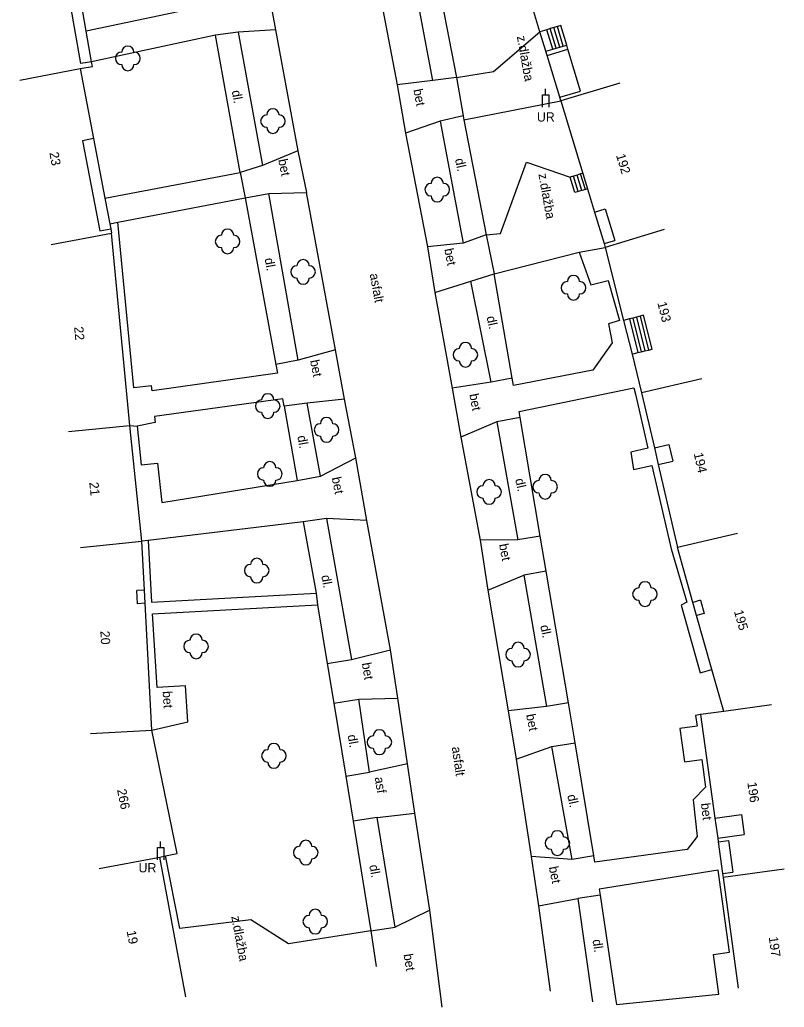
# Model space of a CAD drawing. Extents: x -544674 to -541478, y -1199076 to -1195527.
# Drawn here: x -542529.1 to -542467, y -1198998.4 to -1198918.3 of the extents above; entities that cross this region are included whole.
import ezdxf

# ---------------------------------------------------------------- set-up
doc = ezdxf.new("R2010")
doc.units = 0
for name, color, linetype in [('BUDOVY_MĚŘ', 7, 'Continuous'), ('POMOC_POPIS', 7, 'Continuous'), ('ROZHRANÍ_PLOCH', 7, 'Continuous'), ('ZELEŇ', 7, 'Continuous'), ('ZN_DOPLŇKOVÉ', 7, 'Continuous'), ('Č_POPIS_ORIENT', 7, 'Continuous')]:
    doc.layers.add(name, color=color, linetype=linetype)

msp = doc.modelspace()

# ---------------------------------------------------------------- linework, layer by layer
at = {"layer": 'BUDOVY_MĚŘ'}
for points in [[(-542486.85, -1198919.29), (-542489.77, -1198909.53)], [(-542523.66, -1198919.25), (-542524.33, -1198915.46)], [(-542523.23, -1198921.72), (-542523.66, -1198919.25)], [(-542486.37, -1198920.88), (-542486.85, -1198919.29)], [(-542486.27, -1198921.21), (-542486.37, -1198920.88)], [(-542485.25, -1198924.61), (-542486.27, -1198921.21)], [(-542529.06, -1198923.21), (-542524.15, -1198922.27)], [(-542524.15, -1198922.27), (-542523.16, -1198922.1), (-542523.23, -1198921.72)], [(-542524.15, -1198922.27), (-542523.07, -1198927.96)], [(-542480.38, -1198923.46), (-542485.17, -1198924.89)], [(-542485.17, -1198924.89), (-542485.25, -1198924.61)], [(-542485.17, -1198924.89), (-542483.38, -1198930.78)], [(-542523.07, -1198927.96), (-542522.15, -1198932.8)], [(-542483.38, -1198930.78), (-542483, -1198932.03)], [(-542483, -1198932.03), (-542482.42, -1198933.92)], [(-542522.15, -1198932.8), (-542521.76, -1198934.87)], [(-542482.42, -1198933.92), (-542481.64, -1198936.48)], [(-542521.76, -1198934.87), (-542521.68, -1198935.27)], [(-542521.68, -1198935.27), (-542521.61, -1198935.62)], [(-542526.52, -1198936.55), (-542521.61, -1198935.62)], [(-542520.12, -1198951.23), (-542521.61, -1198935.62)], [(-542476.77, -1198935.32), (-542481.55, -1198936.78)], [(-542481.64, -1198936.48), (-542481.55, -1198936.78)], [(-542481.55, -1198936.78), (-542480.07, -1198942.7)], [(-542480.07, -1198942.7), (-542479.38, -1198945.44)], [(-542479.38, -1198945.44), (-542478.6, -1198948.57)], [(-542473.73, -1198947.44), (-542478.6, -1198948.57)], [(-542478.6, -1198948.57), (-542477.57, -1198953.03)], [(-542525.1, -1198951.71), (-542520.12, -1198951.23)], [(-542519.16, -1198960.62), (-542520.12, -1198951.23)], [(-542477.57, -1198953.03), (-542477.26, -1198954.39)], [(-542477.26, -1198954.39), (-542475.7, -1198961.12)], [(-542470.83, -1198959.99), (-542475.7, -1198961.12)], [(-542524.13, -1198961.13), (-542519.16, -1198960.62)], [(-542518.95, -1198964.57), (-542519.16, -1198960.62)], [(-542474.44, -1198965.58), (-542475.7, -1198961.12)], [(-542518.89, -1198965.65), (-542518.95, -1198964.57)], [(-542518.33, -1198975.93), (-542518.89, -1198965.65)], [(-542474.14, -1198966.64), (-542474.44, -1198965.58)], [(-542472.9, -1198971.01), (-542474.14, -1198966.64)], [(-542471.94, -1198974.42), (-542472.9, -1198971.01)], [(-542471.94, -1198974.42), (-542473.82, -1198974.68)], [(-542468.07, -1198973.88), (-542471.94, -1198974.42)], [(-542473.82, -1198974.68), (-542472.66, -1198983.07)], [(-542523.32, -1198976.2), (-542518.33, -1198975.93)], [(-542517.23, -1198986.14), (-542516.29, -1198985.95), (-542518.33, -1198975.93)], [(-542472.66, -1198983.07), (-542472.43, -1198984.7)], [(-542472.43, -1198984.7), (-542472.39, -1198985)], [(-542472.39, -1198985), (-542472.03, -1198987.57)], [(-542522.61, -1198987.15), (-542517.69, -1198986.24)], [(-542517.69, -1198986.24), (-542517.23, -1198986.14)], [(-542515.59, -1198997.57), (-542517.69, -1198986.24)], [(-542467.03, -1198987.22), (-542471.98, -1198987.9)], [(-542472.03, -1198987.57), (-542471.98, -1198987.9)], [(-542471.98, -1198987.9), (-542470.76, -1198996.87)]]:
    msp.add_lwpolyline(points, dxfattribs=at)
at = {"layer": 'ROZHRANÍ_PLOCH'}
for points in [[(-542500.88, -1198910.85), (-542498.44, -1198923.61)], [(-542495.54, -1198923.25), (-542497.83, -1198911.04)], [(-542496.04, -1198910.62), (-542493.63, -1198923.01)], [(-542523.23, -1198921.72), (-542524.1, -1198921.87), (-542525.41, -1198914.47), (-542524.53, -1198914.32)], [(-542508.92, -1198915.72), (-542508.31, -1198919.14)], [(-542513.65, -1198917.15), (-542523.66, -1198919.25)], [(-542508.31, -1198919.14), (-542511.34, -1198919.32)], [(-542508.31, -1198919.14), (-542506.5, -1198928.96)], [(-542486.3, -1198919.13), (-542486.85, -1198919.29)], [(-542486.01, -1198919.04), (-542486.3, -1198919.13)], [(-542485.82, -1198920.71), (-542486.3, -1198919.13)], [(-542485.73, -1198918.96), (-542486.01, -1198919.04)], [(-542485.54, -1198920.63), (-542486.01, -1198919.04)], [(-542485.44, -1198918.87), (-542485.73, -1198918.96)], [(-542485.25, -1198920.54), (-542485.73, -1198918.96)], [(-542484.68, -1198920.37), (-542485.15, -1198918.78), (-542485.44, -1198918.87)], [(-542484.96, -1198920.45), (-542485.44, -1198918.87)], [(-542513.17, -1198919.58), (-542523.23, -1198921.72)], [(-542511.34, -1198919.32), (-542513.17, -1198919.58)], [(-542511.18, -1198930.7), (-542513.17, -1198919.58)], [(-542511.34, -1198919.32), (-542509.35, -1198930.14)], [(-542493.63, -1198923.01), (-542490.62, -1198922.52), (-542486.85, -1198919.29)], [(-542486.37, -1198920.88), (-542485.82, -1198920.71)], [(-542486.27, -1198921.21), (-542484.58, -1198920.7)], [(-542485.82, -1198920.71), (-542485.54, -1198920.63)], [(-542485.54, -1198920.63), (-542485.25, -1198920.54)], [(-542485.25, -1198920.54), (-542484.96, -1198920.45)], [(-542485.25, -1198924.61), (-542483.56, -1198924.1), (-542484.58, -1198920.7)], [(-542484.96, -1198920.45), (-542484.68, -1198920.37)], [(-542484.58, -1198920.7), (-542484.68, -1198920.37)], [(-542495.54, -1198923.25), (-542498.44, -1198923.61)], [(-542493.63, -1198923.01), (-542495.54, -1198923.25)], [(-542493.63, -1198923.01), (-542493.08, -1198926.1)], [(-542498.44, -1198923.61), (-542497.75, -1198927.53)], [(-542493.02, -1198926.43), (-542485.17, -1198924.89)], [(-542493.08, -1198926.1), (-542494.96, -1198926.54)], [(-542493.08, -1198926.1), (-542493.02, -1198926.43)], [(-542493.02, -1198926.43), (-542491.22, -1198935.76)], [(-542494.96, -1198926.54), (-542497.75, -1198927.53)], [(-542494.96, -1198926.54), (-542493.08, -1198936.44)], [(-542523.07, -1198927.96), (-542523.96, -1198928.13), (-542522.57, -1198935.44), (-542521.68, -1198935.27)], [(-542497.75, -1198927.53), (-542495.98, -1198936.75)], [(-542506.5, -1198928.96), (-542509.35, -1198930.14)], [(-542506.5, -1198928.96), (-542505.78, -1198932.33)], [(-542509.35, -1198930.14), (-542511.18, -1198930.7)], [(-542491.22, -1198935.76), (-542490.05, -1198935.65), (-542487.94, -1198929.87), (-542484.41, -1198931.1)], [(-542522.15, -1198932.8), (-542511.18, -1198930.7)], [(-542511.18, -1198930.7), (-542510.76, -1198932.77)], [(-542484.12, -1198931.01), (-542484.41, -1198931.1)], [(-542483.74, -1198932.25), (-542484.03, -1198932.34), (-542484.41, -1198931.1)], [(-542483.84, -1198930.92), (-542484.12, -1198931.01)], [(-542483.74, -1198932.25), (-542484.12, -1198931.01)], [(-542483.55, -1198930.83), (-542483.84, -1198930.92)], [(-542483.46, -1198932.17), (-542483.84, -1198930.92)], [(-542483.38, -1198930.78), (-542483.55, -1198930.83)], [(-542483.17, -1198932.08), (-542483.55, -1198930.83)], [(-542483.17, -1198932.08), (-542483.46, -1198932.17)], [(-542483, -1198932.03), (-542483.17, -1198932.08)], [(-542521.09, -1198934.74), (-542510.76, -1198932.77)], [(-542510.76, -1198932.77), (-542508.86, -1198932.42)], [(-542510.76, -1198932.77), (-542508.28, -1198946.28)], [(-542508.86, -1198932.42), (-542505.78, -1198932.33)], [(-542506.46, -1198945.93), (-542508.86, -1198932.42)], [(-542503.45, -1198945.09), (-542505.78, -1198932.33)], [(-542483.46, -1198932.17), (-542483.74, -1198932.25)], [(-542482.42, -1198933.92), (-542481.55, -1198933.65)], [(-542481.55, -1198933.65), (-542480.77, -1198936.22)], [(-542521.76, -1198934.87), (-542521.09, -1198934.74)], [(-542508.28, -1198946.28), (-542508.14, -1198946.97), (-542518.32, -1198948.42), (-542518.36, -1198948.02), (-542519.81, -1198948.16), (-542521.09, -1198934.74)], [(-542491.22, -1198935.76), (-542493.08, -1198936.44)], [(-542491.22, -1198935.76), (-542490.57, -1198938.92)], [(-542493.08, -1198936.44), (-542495.98, -1198936.75)], [(-542495.98, -1198936.75), (-542495.39, -1198940.43)], [(-542483.67, -1198937.18), (-542481.55, -1198936.78)], [(-542481.64, -1198936.48), (-542480.77, -1198936.22)], [(-542490.57, -1198938.92), (-542483.67, -1198937.18)], [(-542483.67, -1198937.18), (-542482.73, -1198939.82), (-542481.32, -1198939.47), (-542480.4, -1198942.72), (-542481.29, -1198942.97), (-542480.98, -1198944.51), (-542482.56, -1198946.74), (-542489, -1198947.99), (-542489.1, -1198947.4)], [(-542492.47, -1198939.51), (-542490.57, -1198938.92)], [(-542489.1, -1198947.4), (-542490.57, -1198938.92)], [(-542495.39, -1198940.43), (-542492.47, -1198939.51)], [(-542490.81, -1198947.72), (-542492.47, -1198939.51)], [(-542495.39, -1198940.43), (-542493.97, -1198948.21)], [(-542479.02, -1198942.44), (-542479.31, -1198942.51)], [(-542478.73, -1198942.37), (-542479.02, -1198942.44)], [(-542479.02, -1198942.44), (-542478.34, -1198945.18)], [(-542478.05, -1198945.11), (-542477.75, -1198945.03), (-542478.44, -1198942.29), (-542478.73, -1198942.37)], [(-542478.73, -1198942.37), (-542478.05, -1198945.11)], [(-542479.6, -1198942.58), (-542480.07, -1198942.7)], [(-542479.31, -1198942.51), (-542479.6, -1198942.58)], [(-542479.6, -1198942.58), (-542478.92, -1198945.32)], [(-542479.31, -1198942.51), (-542478.63, -1198945.25)], [(-542503.45, -1198945.09), (-542506.46, -1198945.93)], [(-542502.7, -1198949.1), (-542503.45, -1198945.09)], [(-542479.38, -1198945.44), (-542478.92, -1198945.32)], [(-542478.92, -1198945.32), (-542478.63, -1198945.25)], [(-542478.63, -1198945.25), (-542478.34, -1198945.18)], [(-542478.34, -1198945.18), (-542478.05, -1198945.11)], [(-542506.46, -1198945.93), (-542508.28, -1198946.28)], [(-542490.81, -1198947.72), (-542493.97, -1198948.21)], [(-542489.1, -1198947.4), (-542490.81, -1198947.72)], [(-542493.97, -1198948.21), (-542493.26, -1198952.17)], [(-542488.46, -1198950.58), (-542488.54, -1198950.09), (-542479.23, -1198948.16), (-542479.11, -1198948.69), (-542478.1, -1198953.07), (-542479.49, -1198953.39), (-542479.25, -1198954.8), (-542477.77, -1198954.46), (-542476.21, -1198961.24), (-542474.94, -1198965.55), (-542475.39, -1198965.79), (-542473.84, -1198971.28), (-542472.9, -1198971.01)], [(-542507.6, -1198949.65), (-542507.72, -1198949.06), (-542518.12, -1198950.49), (-542518.07, -1198950.99), (-542519.53, -1198951.27)], [(-542505.75, -1198949.42), (-542507.6, -1198949.65)], [(-542507.6, -1198949.65), (-542506.56, -1198955.68)], [(-542502.7, -1198949.1), (-542505.75, -1198949.42)], [(-542504.66, -1198955.33), (-542505.75, -1198949.42)], [(-542501.79, -1198953.86), (-542502.7, -1198949.1)], [(-542520.12, -1198951.23), (-542519.53, -1198951.27)], [(-542519.53, -1198951.27), (-542519.21, -1198954.42), (-542517.87, -1198954.28), (-542517.53, -1198957.48), (-542506.56, -1198955.68)], [(-542490.35, -1198950.92), (-542493.26, -1198952.17)], [(-542488.46, -1198950.58), (-542490.35, -1198950.92)], [(-542490.35, -1198950.92), (-542488.65, -1198960.5)], [(-542486.83, -1198960.19), (-542488.46, -1198950.58)], [(-542493.26, -1198952.17), (-542491.71, -1198960.53)], [(-542477.57, -1198953.03), (-542476.39, -1198952.76)], [(-542476.39, -1198952.76), (-542476.08, -1198954.12)], [(-542504.66, -1198955.33), (-542501.79, -1198953.86)], [(-542500.89, -1198958.94), (-542501.79, -1198953.86)], [(-542477.26, -1198954.39), (-542476.08, -1198954.12)], [(-542506.56, -1198955.68), (-542504.66, -1198955.33)], [(-542506.07, -1198959.05), (-542518.63, -1198960.56)], [(-542504.18, -1198958.76), (-542506.07, -1198959.05)], [(-542506.07, -1198959.05), (-542505.02, -1198964.83)], [(-542500.89, -1198958.94), (-542504.18, -1198958.76)], [(-542504.18, -1198958.76), (-542502.14, -1198970.21)], [(-542498.98, -1198969.41), (-542500.89, -1198958.94)], [(-542518.63, -1198960.56), (-542519.16, -1198960.62)], [(-542518.63, -1198960.56), (-542518.36, -1198965.55), (-542505.02, -1198964.83)], [(-542488.65, -1198960.5), (-542491.71, -1198960.53)], [(-542491.71, -1198960.53), (-542491.09, -1198964.59)], [(-542486.83, -1198960.19), (-542488.65, -1198960.5)], [(-542486.35, -1198963.05), (-542486.83, -1198960.19)], [(-542486.35, -1198963.05), (-542488.17, -1198963.36)], [(-542484.54, -1198973.73), (-542486.35, -1198963.05)], [(-542491.09, -1198964.59), (-542488.17, -1198963.36)], [(-542488.17, -1198963.36), (-542486.32, -1198974.03)], [(-542518.95, -1198964.57), (-542519.56, -1198964.61)], [(-542519.51, -1198965.69), (-542519.56, -1198964.61)], [(-542505.02, -1198964.83), (-542504.9, -1198965.77)], [(-542491.09, -1198964.59), (-542489.42, -1198974.38)], [(-542518.89, -1198965.65), (-542519.51, -1198965.69)], [(-542473.82, -1198965.4), (-542474.44, -1198965.58)], [(-542473.82, -1198965.4), (-542473.52, -1198966.47)], [(-542518.33, -1198975.93), (-542515.42, -1198975.27), (-542515.61, -1198972.34), (-542517.92, -1198972.47), (-542518.3, -1198966.49), (-542504.9, -1198965.77)], [(-542504.9, -1198965.77), (-542504.11, -1198970.54)], [(-542473.52, -1198966.47), (-542474.14, -1198966.64)], [(-542502.14, -1198970.21), (-542498.98, -1198969.41)], [(-542498.39, -1198973.35), (-542498.98, -1198969.41)], [(-542504.11, -1198970.54), (-542502.14, -1198970.21)], [(-542504.11, -1198970.54), (-542503.58, -1198973.75)], [(-542503.58, -1198973.75), (-542501.55, -1198973.41)], [(-542501.55, -1198973.41), (-542498.39, -1198973.35)], [(-542500.67, -1198979.35), (-542501.55, -1198973.41)], [(-542497.59, -1198978.68), (-542498.39, -1198973.35)], [(-542503.58, -1198973.75), (-542502.6, -1198979.67)], [(-542486.32, -1198974.03), (-542489.42, -1198974.38)], [(-542489.42, -1198974.38), (-542488.79, -1198978.3)], [(-542484.54, -1198973.73), (-542486.32, -1198974.03)], [(-542483.99, -1198976.97), (-542484.54, -1198973.73)], [(-542473.82, -1198974.68), (-542474.22, -1198974.74), (-542474.1, -1198975.6), (-542475.51, -1198975.8), (-542475.12, -1198978.5), (-542473.72, -1198978.31), (-542473.41, -1198980.55), (-542474.42, -1198981.59), (-542474.09, -1198984.55), (-542474.91, -1198985.62), (-542482.4, -1198986.63), (-542482.48, -1198986.14)], [(-542488.79, -1198978.3), (-542485.88, -1198977.25)], [(-542485.88, -1198977.25), (-542483.99, -1198976.97)], [(-542484.24, -1198986.44), (-542485.88, -1198977.25)], [(-542482.48, -1198986.14), (-542483.99, -1198976.97)], [(-542488.79, -1198978.3), (-542487.56, -1198986.19)], [(-542497.59, -1198978.68), (-542500.67, -1198979.35)], [(-542497.01, -1198982.67), (-542497.59, -1198978.68)], [(-542502.6, -1198979.67), (-542500.67, -1198979.35)], [(-542502.6, -1198979.67), (-542502, -1198983.31)], [(-542500.07, -1198983.02), (-542502, -1198983.31)], [(-542502, -1198983.31), (-542500.57, -1198992.2)], [(-542500.07, -1198983.02), (-542497.01, -1198982.67)], [(-542498.59, -1198991.92), (-542500.07, -1198983.02)], [(-542495.8, -1198990.54), (-542497.01, -1198982.67)], [(-542472.66, -1198983.07), (-542470.5, -1198982.77)], [(-542470.5, -1198982.77), (-542470.28, -1198984.4)], [(-542472.43, -1198984.7), (-542470.28, -1198984.4)], [(-542472.39, -1198985), (-542471.55, -1198984.88)], [(-542471.55, -1198984.88), (-542471.19, -1198987.46)], [(-542500.57, -1198992.2), (-542507.25, -1198993.26), (-542510.32, -1198991.32), (-542516.08, -1198992.03), (-542517.23, -1198986.14)], [(-542487.56, -1198986.19), (-542486.97, -1198990.19)], [(-542484.24, -1198986.44), (-542487.56, -1198986.19)], [(-542482.48, -1198986.14), (-542484.24, -1198986.44)], [(-542480.71, -1198997.69), (-542480.64, -1198998.18), (-542472.35, -1198997.36), (-542472.77, -1198994.13), (-542471.47, -1198993.95), (-542472.4, -1198987.3), (-542482.06, -1198988.82), (-542481.98, -1198989.32)], [(-542472.03, -1198987.57), (-542471.19, -1198987.46)], [(-542486.97, -1198990.19), (-542483.79, -1198989.59)], [(-542481.98, -1198989.32), (-542483.79, -1198989.59)], [(-542483.79, -1198989.59), (-542482.58, -1198997.97)], [(-542481.98, -1198989.32), (-542480.71, -1198997.69)], [(-542495.8, -1198990.54), (-542498.59, -1198991.92)], [(-542494.79, -1198998.41), (-542495.8, -1198990.54)], [(-542486.97, -1198990.19), (-542486.03, -1198997.1)], [(-542500.57, -1198992.2), (-542498.59, -1198991.92)], [(-542500.57, -1198992.2), (-542500.14, -1198995.1)]]:
    msp.add_lwpolyline(points, dxfattribs=at)
at = {"layer": 'ZELEŇ'}
for centre in [(-542520.29, -1198921.45), (-542508.52, -1198926.54), (-542495.19, -1198932.1), (-542512.2, -1198936.3), (-542506.07, -1198938.77), (-542484.13, -1198940.06), (-542492.9, -1198945.49), (-542508.94, -1198949.65), (-542504.17, -1198951.58), (-542508.77, -1198955.16), (-542490.98, -1198956.62), (-542486.43, -1198956.2), (-542509.83, -1198962.99), (-542478.33, -1198964.9), (-542514.75, -1198969.14), (-542488.63, -1198969.81), (-542499.88, -1198976.91), (-542508.44, -1198978.02), (-542485.44, -1198985.1), (-542505.85, -1198985.87), (-542505.08, -1198991.46)]:
    msp.add_circle(centre, 0.0005, dxfattribs=at)
for centre, start, end in [((-542520.29, -1198920.95), 0, 179.99999), ((-542520.79, -1198921.45), 89.99999, 269.99999), ((-542519.79, -1198921.45), 270, 89.99999), ((-542520.29, -1198921.95), 179.99999, 359.99999), ((-542508.52, -1198926.04), 0, 179.99999), ((-542509.02, -1198926.54), 89.99999, 269.99999), ((-542508.02, -1198926.54), 270, 89.99999), ((-542508.52, -1198927.04), 179.99999, 359.99999), ((-542495.19, -1198931.6), 0, 179.99999), ((-542495.69, -1198932.1), 89.99999, 269.99999), ((-542494.69, -1198932.1), 270, 89.99999), ((-542495.19, -1198932.6), 179.99999, 359.99999), ((-542512.7, -1198936.3), 89.99999, 269.99999), ((-542512.2, -1198935.8), 0, 179.99999), ((-542511.7, -1198936.3), 270, 89.99999), ((-542512.2, -1198936.8), 179.99999, 359.99999), ((-542506.57, -1198938.77), 89.99999, 269.99999), ((-542506.07, -1198938.27), 0, 179.99999), ((-542505.57, -1198938.77), 270, 89.99999), ((-542506.07, -1198939.27), 179.99999, 359.99999), ((-542484.13, -1198939.56), 0, 179.99999), ((-542484.63, -1198940.06), 89.99999, 269.99999), ((-542483.63, -1198940.06), 270, 89.99999), ((-542484.13, -1198940.56), 179.99999, 359.99999), ((-542492.9, -1198944.99), 0, 179.99999), ((-542493.4, -1198945.49), 89.99999, 269.99999), ((-542492.4, -1198945.49), 270, 89.99999), ((-542492.9, -1198945.99), 179.99999, 359.99999), ((-542508.94, -1198949.15), 0, 179.99999), ((-542509.44, -1198949.65), 89.99999, 269.99999), ((-542508.44, -1198949.65), 270, 89.99999), ((-542508.94, -1198950.15), 179.99999, 359.99999), ((-542504.67, -1198951.58), 89.99999, 269.99999), ((-542504.17, -1198951.08), 0, 179.99999), ((-542503.67, -1198951.58), 270, 89.99999), ((-542504.17, -1198952.08), 179.99999, 359.99999), ((-542508.77, -1198954.66), 0, 179.99999), ((-542509.27, -1198955.16), 89.99999, 269.99999), ((-542508.27, -1198955.16), 270, 89.99999), ((-542486.43, -1198955.7), 0, 179.99999), ((-542508.77, -1198955.66), 179.99999, 359.99999), ((-542490.98, -1198956.12), 0, 179.99999), ((-542486.93, -1198956.2), 89.99999, 269.99999), ((-542485.93, -1198956.2), 270, 89.99999), ((-542491.48, -1198956.62), 89.99999, 269.99999), ((-542490.48, -1198956.62), 270, 89.99999), ((-542486.43, -1198956.7), 179.99999, 359.99999), ((-542490.98, -1198957.12), 179.99999, 359.99999), ((-542510.33, -1198962.99), 89.99999, 269.99999), ((-542509.83, -1198962.49), 0, 179.99999), ((-542509.33, -1198962.99), 270, 89.99999), ((-542509.83, -1198963.49), 179.99999, 359.99999), ((-542478.33, -1198964.4), 0, 179.99999), ((-542478.83, -1198964.9), 89.99999, 269.99999), ((-542477.83, -1198964.9), 270, 89.99999), ((-542478.33, -1198965.4), 179.99999, 359.99999), ((-542515.25, -1198969.14), 89.99999, 269.99999), ((-542514.75, -1198968.64), 0, 179.99999), ((-542514.25, -1198969.14), 270, 89.99999), ((-542488.63, -1198969.31), 0, 179.99999), ((-542514.75, -1198969.64), 179.99999, 359.99999), ((-542489.13, -1198969.81), 89.99999, 269.99999), ((-542488.13, -1198969.81), 270, 89.99999), ((-542488.63, -1198970.31), 179.99999, 359.99999), ((-542499.88, -1198976.41), 0, 179.99999), ((-542500.38, -1198976.91), 89.99999, 269.99999), ((-542499.38, -1198976.91), 270, 89.99999), ((-542508.94, -1198978.02), 89.99999, 269.99999), ((-542508.44, -1198977.52), 0, 179.99999), ((-542507.94, -1198978.02), 270, 89.99999), ((-542499.88, -1198977.41), 179.99999, 359.99999), ((-542508.44, -1198978.52), 179.99999, 359.99999), ((-542485.44, -1198984.6), 0, 179.99999), ((-542505.85, -1198985.37), 0, 179.99999), ((-542485.94, -1198985.1), 89.99999, 269.99999), ((-542484.94, -1198985.1), 270, 89.99999), ((-542506.35, -1198985.87), 89.99999, 269.99999), ((-542505.35, -1198985.87), 270, 89.99999), ((-542485.44, -1198985.6), 179.99999, 359.99999), ((-542505.85, -1198986.37), 179.99999, 359.99999), ((-542505.08, -1198990.96), 0, 179.99999), ((-542505.58, -1198991.46), 89.99999, 269.99999), ((-542504.58, -1198991.46), 270, 89.99999), ((-542505.08, -1198991.96), 179.99999, 359.99999)]:
    msp.add_arc(centre, 0.5, start, end, dxfattribs=at)
at = {"layer": 'ZN_DOPLŇKOVÉ'}
for p, q in [((-542486.39, -1198924.41), (-542486.39, -1198923.91)), ((-542517.63, -1198985.46), (-542517.63, -1198984.96))]:
    msp.add_line(p, q, dxfattribs=at)
for points in [[(-542486.64, -1198925.41), (-542486.64, -1198924.41), (-542486.14, -1198924.41), (-542486.14, -1198925.41)], [(-542517.88, -1198986.46), (-542517.88, -1198985.46), (-542517.38, -1198985.46), (-542517.38, -1198986.46)]]:
    msp.add_lwpolyline(points, dxfattribs=at)

# ---------------------------------------------------------------- texts
at = {"layer": 'POMOC_POPIS'}
for s, rotation, p in [('z.dlažba', 280.11001, (-542488.73, -1198919.68)), ('dl.', 280.30001, (-542511.86, -1198924.1)), ('bet', 281.07997, (-542497.13, -1198924)), ('bet', 281.35998, (-542508.09, -1198929.68)), ('dl.', 282.33, (-542493.75, -1198929.64)), ('z.dlažba', 280.11001, (-542486.98, -1198930.85)), ('bet', 281.07997, (-542494.62, -1198936.93)), ('dl.', 280.30001, (-542509.2, -1198937.7)), ('asfalt', 280.35003, (-542500.67, -1198938.95)), ('dl.', 282.33, (-542491.19, -1198942.43)), ('bet', 281.35998, (-542505.51, -1198945.97)), ('bet', 281.07997, (-542492.59, -1198948.71)), ('dl.', 280.30001, (-542506.54, -1198952.1)), ('bet', 281.35998, (-542503.75, -1198955.47)), ('dl.', 282.33, (-542488.87, -1198955.6)), ('bet', 281.07997, (-542490.18, -1198960.88)), ('dl.', 280.30001, (-542504.6, -1198963.42)), ('dl.', 282.33, (-542486.84, -1198967.48)), ('bet', 279.38998, (-542501.31, -1198970.51)), ('bet', 273.09999, (-542517.46, -1198972.78)), ('bet', 281.07997, (-542487.98, -1198974.69)), ('dl.', 280.30001, (-542502.47, -1198976.36)), ('asfalt', 278.27002, (-542494.01, -1198977.32)), ('asf', 279.38998, (-542500.27, -1198979.78)), ('dl.', 282.33, (-542484.64, -1198981.23)), ('bet', 276.36, (-542473.79, -1198981.88)), ('dl.', 280.30001, (-542500.7, -1198986.91)), ('bet', 281.07997, (-542486.13, -1198987.05)), ('z.dlažba', 280.50003, (-542511.9, -1198991.05)), ('dl.', 278.22, (-542482.59, -1198992.95)), ('bet', 279.38998, (-542497.92, -1198994.13))]:
    msp.add_text(s, height=0.75, rotation=rotation, dxfattribs=at).set_placement(p)
for p in [(-542487.1, -1198926.58), (-542519.42, -1198987.47)]:
    msp.add_text('UR', height=0.75, dxfattribs=at).set_placement(p)
at = {"layer": 'Č_POPIS_ORIENT'}
for s, rotation, p in [('23', 280.75001, (-542526.66, -1198929.11)), ('192', 286.92999, (-542480.69, -1198929.31)), ('193', 284.05001, (-542477.33, -1198941.29)), ('22', 275.44998, (-542524.65, -1198943.24)), ('194', 283.00998, (-542474.38, -1198953.51)), ('21', 275.83999, (-542523.42, -1198955.85)), ('195', 285.8, (-542471.12, -1198966.3)), ('20', 273.09999, (-542522.52, -1198967.9)), ('266', 281.50998, (-542521.17, -1198980.78)), ('196', 277.92, (-542470.03, -1198980.19)), ('19', 280.50003, (-542520.39, -1198992.25)), ('197', 277.78002, (-542468.29, -1198992.72))]:
    msp.add_text(s, height=0.75, rotation=rotation, dxfattribs=at).set_placement(p)

doc.saveas('drawing.dxf')
